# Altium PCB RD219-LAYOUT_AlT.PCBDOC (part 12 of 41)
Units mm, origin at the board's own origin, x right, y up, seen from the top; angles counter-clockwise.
Board outline 209.75 x 159.97 mm, 2 copper layers (TOP, BOTTOM), stack 0 mm thick; 398 components, 199 nets, 1469 pads, 0 vias.
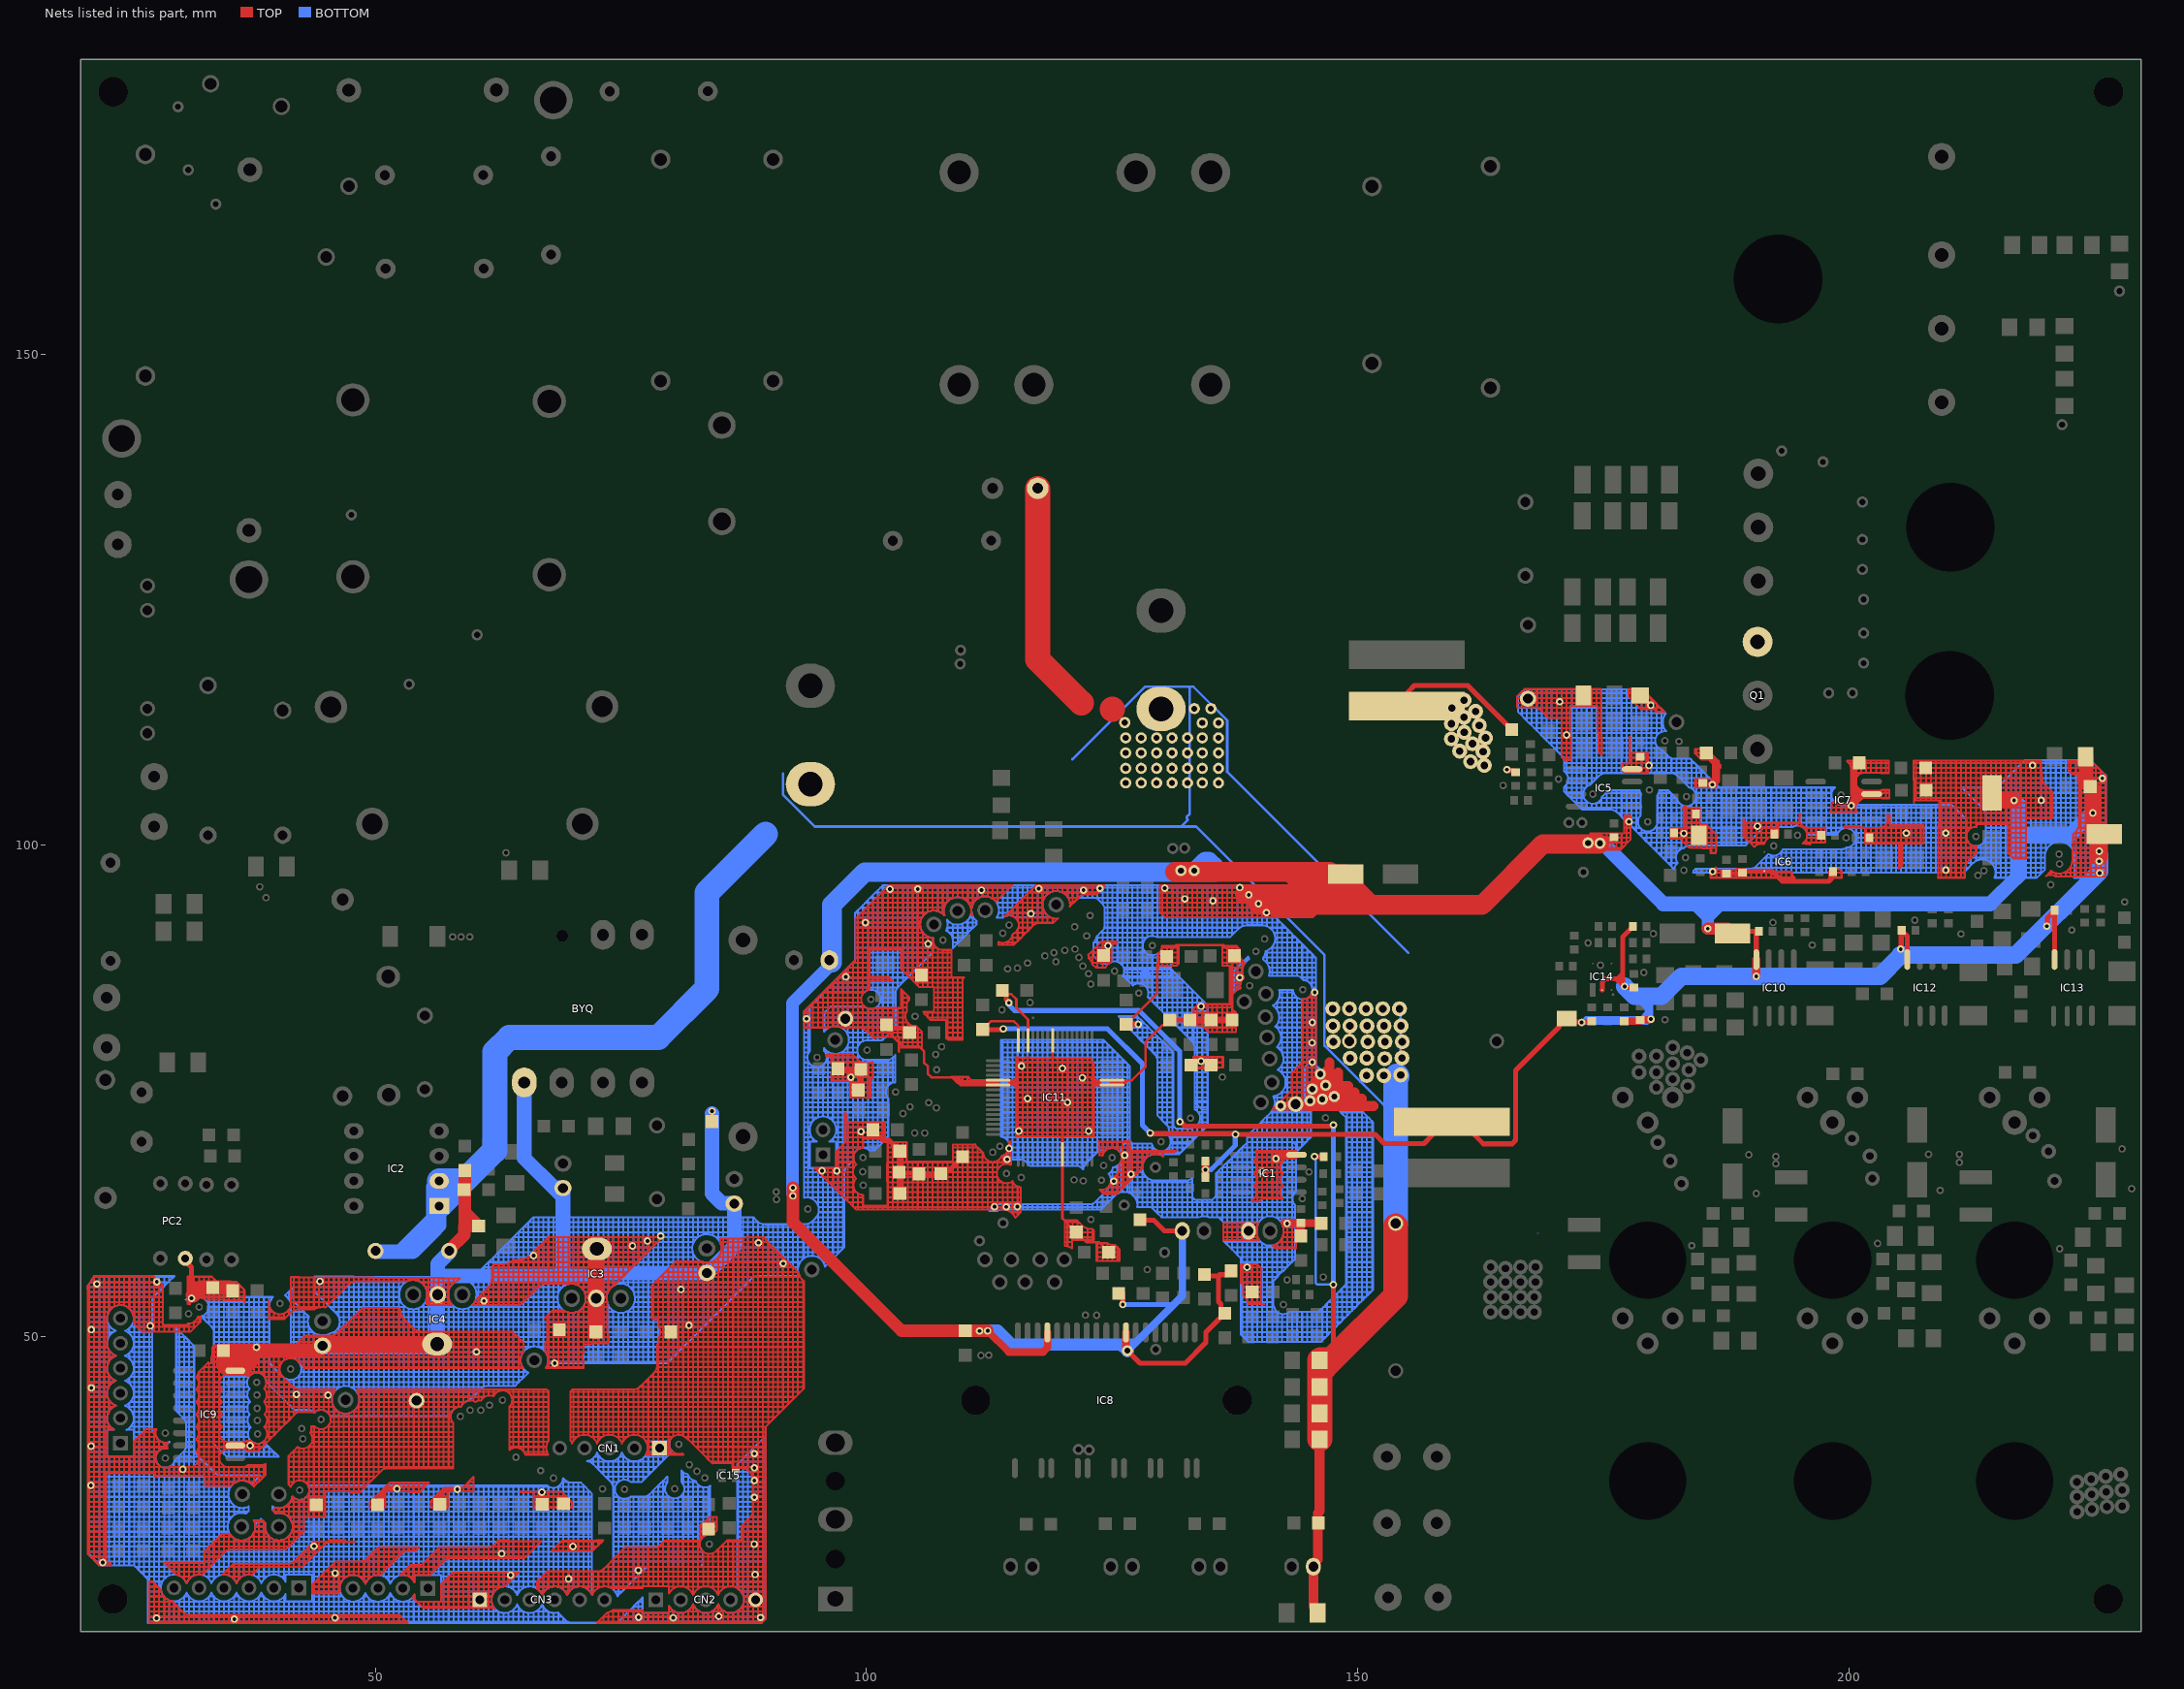
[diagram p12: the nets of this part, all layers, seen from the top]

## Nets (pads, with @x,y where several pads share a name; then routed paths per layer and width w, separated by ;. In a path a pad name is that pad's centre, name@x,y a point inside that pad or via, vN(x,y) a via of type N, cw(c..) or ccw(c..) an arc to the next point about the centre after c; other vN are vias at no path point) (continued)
GND: (continued)
  TOP w0.203: 90.993,56.576 90.993,57.084 ; 90.993,56.576 91.501,56.576 ; 90.993,57.084 90.993,57.592 ; 90.993,57.084 pad.@91.501,57.084 ; 90.993,57.592 90.993,58.1 ; 90.993,57.592 pad.@91.501,57.592 ; 90.993,58.1 91.501,58.1 ; 90.993,58.1 90.993,58.608 ; 90.993,58.608 91.006,58.608 ; 90.993,58.608 90.993,58.621 ; 90.993,58.621 91.006,58.608 ; 91.006,58.608 91.501,58.113 ; 91.247,42.352 91.501,42.606 ; 91.501,42.606 91.501,42.86 ; 91.501,42.606 91.755,42.86 ; 91.501,42.86 91.501,43.368 ; 91.501,42.86 91.755,42.86 ; 91.501,43.368 91.501,43.876 ; 91.501,43.368 92.009,43.368 ; 91.501,43.876 91.501,44.384 ; 91.501,43.876 92.009,43.876 ; 91.501,44.384 91.501,44.892 ; 91.501,44.384 92.009,44.384 ; 91.501,44.892 91.501,45.4 ; 91.501,44.892 92.009,44.892 ; 91.501,45.4 91.501,45.908 ; 91.501,45.4 92.009,45.4 ; 91.501,45.908 91.501,46.416 ; 91.501,45.908 92.009,45.908 ; 91.501,46.416 91.501,46.924 ; 91.501,46.416 92.009,46.416 ; 91.501,46.924 91.501,47.432 ; 91.501,46.924 92.009,46.924 ; 91.501,47.432 91.501,47.94 ; 91.501,47.432 92.009,47.432 ; 91.501,47.94 91.501,48.448 ; 91.501,47.94 92.009,47.94 ; 91.501,48.448 91.501,48.956 ; 91.501,48.448 92.009,48.448 ; 91.501,48.956 91.501,49.464 ; 91.501,48.956 92.009,48.956 ; 91.501,49.464 91.501,49.972 ; 91.501,49.464 92.009,49.464 ; 91.501,49.972 91.501,50.48 ; 91.501,49.972 92.009,49.972 ; 91.501,50.48 91.501,50.988 ; 91.501,50.48 92.009,50.48 ; 91.501,50.988 91.501,51.496 ; 91.501,50.988 92.009,50.988 ; 91.501,51.496 91.501,52.004 ; 91.501,51.496 92.009,51.496 ; 91.501,52.004 91.501,52.512 ; 91.501,52.004 92.009,52.004 ; 91.501,52.512 91.501,53.02 ; 91.501,52.512 92.009,52.512 ; 91.501,53.02 91.501,53.528 ; 91.501,53.02 92.009,53.02 ; 91.501,53.528 91.501,54.036 ; 91.501,53.528 92.009,53.528 ; 91.501,54.036 91.501,54.544 ; 91.501,54.036 92.009,54.036 ; 91.501,54.544 91.501,55.052 ; 91.501,54.544 92.009,54.544 ; 91.501,55.052 91.501,55.56 ; 91.501,55.052 92.009,55.052 ; 91.501,55.56 91.501,56.068 ; 91.501,55.56 92.009,55.56 ; 91.501,56.068 91.501,56.576 ; 91.501,56.068 92.009,56.068 ; 91.501,56.576 pad.@91.501,57.084 ; 91.501,56.576 92.009,56.576 ; pad.@91.501,57.084 pad.@91.501,57.592 ; pad.@91.501,57.084 92.009,57.084 ; pad.@91.501,57.592 91.501,58.1 ; pad.@91.501,57.592 92.009,57.592 ; 91.501,58.1 91.514,58.1 ; 91.501,58.1 91.501,58.113 ; 91.501,58.113 91.514,58.1 ; 91.514,58.1 92.009,57.605 ; 91.755,42.86 92.009,43.114 ; 92.009,43.114 92.009,43.368 ; 92.009,43.114 92.263,43.368 ; 92.009,43.368 92.009,43.876 ; 92.009,43.368 92.263,43.368 ; 92.009,43.876 92.009,44.384 ; 92.009,43.876 92.517,43.876 ; 92.009,44.384 92.009,44.892 ; 92.009,44.384 92.517,44.384 ; 92.009,44.892 92.009,45.4 ; 92.009,44.892 92.517,44.892 ; 92.009,45.4 92.009,45.908 ; 92.009,45.4 92.517,45.4 ; 92.009,45.908 92.009,46.416 ; 92.009,45.908 92.517,45.908 ; 92.009,46.416 92.009,46.924 ; 92.009,46.416 92.517,46.416 ; 92.009,46.924 92.009,47.432 ; 92.009,46.924 92.517,46.924 ; 92.009,47.432 92.009,47.94 ; 92.009,47.432 92.517,47.432 ; 92.009,47.94 92.009,48.448 ; 92.009,47.94 92.517,47.94 ; 92.009,48.448 92.009,48.956 ; 92.009,48.448 92.517,48.448 ; 92.009,48.956 92.009,49.464 ; 92.009,48.956 92.517,48.956 ; 92.009,49.464 92.009,49.972 ; 92.009,49.464 92.517,49.464 ; 92.009,49.972 92.009,50.48 ; 92.009,49.972 92.517,49.972 ; 92.009,50.48 92.009,50.988 ; 92.009,50.48 92.517,50.48 ; 92.009,50.988 92.009,51.496 ; 92.009,50.988 92.517,50.988 ; 92.009,51.496 92.009,52.004 ; 92.009,51.496 92.517,51.496 ; 92.009,52.004 92.009,52.512 ; 92.009,52.004 92.517,52.004 ; 92.009,52.512 92.009,53.02 ; 92.009,52.512 92.517,52.512 ; 92.009,53.02 92.009,53.528 ; 92.009,53.02 92.517,53.02 ; 92.009,53.528 92.009,54.036 ; 92.009,53.528 92.517,53.528 ; 92.009,54.036 92.009,54.544 ; 92.009,54.036 92.517,54.036 ; 92.009,54.544 92.009,55.052 ; 92.009,54.544 92.517,54.544 ; 92.009,55.052 92.009,55.56 ; 92.009,55.052 92.517,55.052 ; 92.009,55.56 92.009,56.068 ; 92.009,55.56 92.517,55.56 ; 92.009,56.068 92.009,56.576 ; 92.009,56.068 92.517,56.068 ; 92.009,56.576 92.009,57.084 ; 92.009,56.576 92.517,56.576 ; 92.009,57.084 92.009,57.592 ; 92.009,57.084 92.517,57.084 ; 92.009,57.592 92.009,57.605 ; 92.009,57.592 92.022,57.592 ; 92.009,57.605 92.022,57.592 ; 92.022,57.592 92.517,57.097 ; 92.263,43.368 92.517,43.622 ; 92.517,43.622 92.517,43.876 ; 92.517,43.622 92.771,43.876 ; 92.517,43.876 92.517,44.384 ; 92.517,43.876 92.771,43.876 ; 92.517,44.384 93.025,44.384 ; 92.517,44.384 92.517,44.892 ; 92.517,44.892 93.025,44.892 ; 92.517,44.892 92.517,45.4 ; 92.517,45.4 92.517,45.908 ; 92.517,45.4 93.025,45.4 ; 92.517,45.908 92.517,46.416 ; 92.517,45.908 93.025,45.908 ; 92.517,46.416 93.025,46.416 ; 92.517,46.416 92.517,46.924 ; 92.517,46.924 93.025,46.924 ; 92.517,46.924 92.517,47.432 ; 92.517,47.432 92.517,47.94 ; 92.517,47.432 93.025,47.432 ; 92.517,47.94 92.517,48.448 ; 92.517,47.94 93.025,47.94 ; 92.517,48.448 92.517,48.956 ; 92.517,48.448 93.025,48.448 ; 92.517,48.956 92.517,49.464 ; 92.517,48.956 93.025,48.956 ; 92.517,49.464 92.517,49.972 ; 92.517,49.464 93.025,49.464 ; 92.517,49.972 93.025,49.972 ; 92.517,49.972 92.517,50.48 ; 92.517,50.48 92.517,50.988 ; 92.517,50.48 93.025,50.48 ; 92.517,50.988 93.025,50.988 ; 92.517,50.988 92.517,51.496 ; 92.517,51.496 92.517,52.004 ; 92.517,51.496 93.025,51.496 ; 92.517,52.004 93.025,52.004 ; 92.517,52.004 92.517,52.512 ; 92.517,52.512 92.517,53.02 ; 92.517,52.512 93.025,52.512 ; 92.517,53.02 93.025,53.02 ; 92.517,53.02 92.517,53.528 ; 92.517,53.528 92.517,54.036 ; 92.517,53.528 93.025,53.528 ; 92.517,54.036 92.517,54.544 ; 92.517,54.036 93.025,54.036 ; 92.517,54.544 92.517,55.052 ; 92.517,54.544 93.025,54.544 ; 92.517,55.052 93.025,55.052 ; 92.517,55.052 92.517,55.56 ; 92.517,55.56 93.025,55.56 ; 92.517,55.56 92.517,56.068 ; 92.517,56.068 92.517,56.576 ; 92.517,56.068 93.025,56.068 ; 92.517,56.576 93.025,56.576 ; 92.517,56.576 92.517,57.084 ; 92.517,57.084 92.517,57.097 ; 92.517,57.084 92.53,57.084 ; 92.517,57.097 92.53,57.084 ; 92.53,57.084 93.025,56.589 ; 92.771,43.876 93.025,44.13 ; 93.025,44.13 93.279,44.384 ; 93.025,44.13 93.025,44.384 ; 93.025,44.384 93.279,44.384 ; 93.025,44.384 93.025,44.892 ; 93.025,44.892 93.533,44.892 ; 93.025,44.892 93.025,45.4 ; 93.025,45.4 93.025,45.908 ; 93.025,45.4 93.533,45.4 ; 93.025,45.908 93.025,46.416 ; 93.025,45.908 93.533,45.908 ; 93.025,46.416 93.533,46.416 ; 93.025,46.416 93.025,46.924 ; 93.025,46.924 93.533,46.924 ; 93.025,46.924 93.025,47.432 ; 93.025,47.432 93.025,47.94 ; 93.025,47.432 93.533,47.432 ; 93.025,47.94 93.025,48.448 ; 93.025,47.94 93.533,47.94 ; 93.025,48.448 93.025,48.956 ; 93.025,48.448 93.533,48.448 ; 93.025,48.956 93.025,49.464 ; 93.025,48.956 93.533,48.956 ; 93.025,49.464 93.025,49.972 ; 93.025,49.464 93.533,49.464 ; 93.025,49.972 93.533,49.972 ; 93.025,49.972 93.025,50.48 ; 93.025,50.48 93.025,50.988 ; 93.025,50.48 93.533,50.48 ; 93.025,50.988 93.533,50.988 ; 93.025,50.988 93.025,51.496 ; 93.025,51.496 93.025,52.004 ; 93.025,51.496 93.533,51.496 ; 93.025,52.004 93.533,52.004 ; 93.025,52.004 93.025,52.512 ; 93.025,52.512 93.025,53.02 ; 93.025,52.512 93.533,52.512 ; 93.025,53.02 93.533,53.02 ; 93.025,53.02 93.025,53.528 ; 93.025,53.528 93.025,54.036 ; 93.025,53.528 93.533,53.528 ; 93.025,54.036 93.025,54.544 ; 93.025,54.036 93.533,54.036 ; 93.025,54.544 93.025,55.052 ; 93.025,54.544 93.533,54.544 ; 93.025,55.052 93.533,55.052 ; 93.025,55.052 93.025,55.56 ; 93.025,55.56 93.533,55.56 ; 93.025,55.56 93.025,56.068 ; 93.025,56.068 93.025,56.576 ; 93.025,56.068 93.246,56.068 ; 93.025,56.576 93.025,56.589 ; 93.025,56.576 93.038,56.576 ; 93.025,56.589 93.038,56.576 ; 93.246,56.068 ccw(c94.422,56.83) 93.247,56.067 ccw(c94.422,56.83) 93.533,55.746 ; 93.279,44.384 93.533,44.638 ; 93.533,44.638 93.533,44.892 ; 93.533,44.638 93.66,44.765 93.66,44.892 ; 93.533,44.892 93.533,45.4 ; 93.533,44.892 93.66,44.892 ; 93.533,45.4 93.533,45.908 ; 93.533,45.4 93.66,45.4 ; 93.533,45.908 93.533,46.416 ; 93.533,45.908 93.66,45.908 ; 93.533,46.416 93.533,46.924 ; 93.533,46.416 93.66,46.416 ; 93.533,46.924 93.533,47.432 ; 93.533,46.924 93.66,46.924 ; 93.533,47.432 93.533,47.94 ; 93.533,47.432 93.66,47.432 ; 93.533,47.94 93.533,48.448 ; 93.533,47.94 93.66,47.94 ; 93.533,48.448 93.533,48.956 ; 93.533,48.448 93.66,48.448 ; 93.533,48.956 93.533,49.464 ; 93.533,48.956 93.66,48.956 ; 93.533,49.464 93.533,49.972 ; 93.533,49.464 93.66,49.464 ; 93.533,49.972 93.533,50.48 ; 93.533,50.48 93.533,50.988 ; 93.533,50.48 93.66,50.48 ; 93.533,50.988 93.66,50.988 ; 93.533,50.988 93.533,51.496 ; 93.533,51.496 93.533,52.004 ; 93.533,51.496 93.66,51.496 ; 93.533,52.004 93.66,52.004 ; 93.533,52.004 93.533,52.512 ; 93.533,52.512 93.533,53.02 ; 93.533,52.512 93.66,52.512 ; 93.533,53.02 93.533,53.528 ; 93.533,53.02 93.66,53.02 ; 93.533,53.528 93.533,54.036 ; 93.533,53.528 93.66,53.528 ; 93.533,54.036 93.533,54.544 ; 93.533,54.036 93.66,54.036 ; 93.533,54.544 93.533,55.052 ; 93.533,54.544 93.66,54.544 ; 93.533,55.052 93.533,55.56 ; 93.533,55.052 93.66,55.052 ; 93.533,55.56 93.66,55.56 ; 93.533,55.56 93.533,55.746 ; 93.66,44.892 93.66,45.4 ; 93.66,45.4 93.66,45.908 ; 93.66,45.908 93.66,46.416 ; 93.66,46.416 93.66,46.924 ; 93.66,46.924 93.66,47.432 ; 93.66,47.432 93.66,47.94 ; 93.66,47.94 93.66,48.448 ; 93.66,48.448 93.66,48.956 ; 93.66,48.956 93.66,49.464 ; 93.66,49.464 93.66,50.48 ; 93.66,50.48 93.66,50.988 ; 93.66,50.988 93.66,51.496 ; 93.66,51.496 93.66,52.004 ; 93.66,52.004 93.66,52.512 ; 93.66,52.512 93.66,53.02 ; 93.66,53.02 93.66,53.528 ; 93.66,53.528 93.66,54.036 ; 93.66,54.036 93.66,54.544 ; 93.66,54.544 93.66,55.052 ; 93.66,55.052 93.66,55.56 ; 93.66,81.468 93.66,81.976 ; 93.66,81.468 93.66,81.44 94.041,81.44 ; 93.66,81.468 94.041,81.468 ; 93.66,81.976 94.041,81.976 ; 93.66,81.976 pad.@93.66,82.484 ; pad.@93.66,82.484 93.66,82.992 ; pad.@93.66,82.484 pad.@94.041,82.484 ; 93.66,82.992 93.66,83.119 94.041,83.5 ; 93.66,82.992 94.041,82.992 ; 94.041,81.44 94.041,81.468 ; 94.041,81.44 94.549,81.44 ; 94.041,81.468 94.041,81.976 ; 94.041,81.468 94.549,81.468 ; 94.041,81.976 94.549,81.976 ; 94.041,81.976 pad.@94.041,82.484 ; pad.@94.041,82.484 94.041,82.992 ; pad.@94.041,82.484 94.549,82.484 ; 94.041,82.992 94.041,83.5 ; 94.041,82.992 94.549,82.992 ; 94.041,83.5 94.549,83.5 ; 94.041,83.5 94.549,84.008 ; 94.549,81.44 94.549,81.468 ; 94.549,81.44 95.057,81.44 ; 94.549,81.468 94.549,81.976 ; 94.549,81.468 95.057,81.468 ; 94.549,81.976 94.549,82.484 ; 94.549,81.976 95.057,81.976 ; 94.549,82.484 94.549,82.992 ; 94.549,82.484 95.057,82.484 ; 94.549,82.992 94.549,83.5 ; 94.549,82.992 95.057,82.992 ; 94.549,83.5 94.549,84.008 ; 94.549,83.5 95.057,83.5 ; 94.549,84.008 95.057,84.516 ; 94.549,84.008 95.057,84.008 ; 95.057,66.821 pad.@95.142,66.736 ; 95.057,66.821 94.716,67.162 95.057,67.162 ; 95.057,66.821 95.057,67.162 ; 95.057,67.162 pad.@95.565,67.162 ; 95.057,81.44 95.057,81.468 ; 95.057,81.44 95.565,81.44 ; 95.057,81.468 95.057,81.976 ; 95.057,81.468 95.565,81.468 ; 95.057,81.976 95.057,82.484 ; 95.057,81.976 95.565,81.976 ; 95.057,82.484 95.057,82.992 ; 95.057,82.484 95.565,82.484 ; 95.057,82.992 95.057,83.5 ; 95.057,82.992 95.565,82.992 ; 95.057,83.5 95.057,84.008 ; 95.057,83.5 95.565,83.5 ; 95.057,84.008 95.057,84.516 ; 95.057,84.008 95.565,84.008 ; 95.057,84.516 95.565,85.024 ; 95.057,84.516 95.565,84.516 ; pad.@95.142,66.736 95.565,66.313 ; pad.@95.142,66.736 pad.@95.565,66.736 ; 95.565,66.313 pad.@95.565,66.736 ; 95.565,66.313 95.65,66.228 ; pad.@95.565,66.736 96.073,66.736 ; pad.@95.565,66.736 pad.@95.565,67.162 ; pad.@95.565,67.162 96.073,67.162 ; 95.565,81.44 96.073,81.44 ; 95.565,81.44 95.565,81.468 ; 95.565,81.468 96.073,81.468 ; 95.565,81.468 95.565,81.976 ; 95.565,81.976 95.565,82.484 ; 95.565,81.976 96.073,81.976 ; 95.565,82.484 95.565,82.992 ; 95.565,82.484 96.073,82.484 ; 95.565,82.992 96.073,82.992 ; 95.565,82.992 95.565,83.5 ; 95.565,83.5 95.565,84.008 ; 95.565,83.5 96.073,83.5 ; 95.565,84.008 95.565,84.516 ; 95.565,84.008 96.073,84.008 ; 95.565,84.516 95.565,85.024 ; 95.565,84.516 96.073,84.516 ; 95.565,85.024 96.073,85.532 ; 95.565,85.024 96.073,85.024 ; 95.65,66.228 96.073,65.805 ; 95.65,66.228 96.073,66.228 ; 95.941,78.529 96.073,78.529 ; 96.073,65.805 96.158,65.72 ; 96.073,65.805 96.073,66.228 ; 96.073,66.228 96.073,66.736 ; 96.073,66.228 96.581,66.228 ; 96.073,66.736 96.073,67.162 ; 96.073,66.736 96.581,66.736 ; 96.073,67.162 96.581,67.162 ; 96.073,78.529 96.436,78.529 96.436,78.42 ; 96.073,78.529 96.073,78.736 ; 96.073,78.736 96.581,78.736 ; 96.073,81.44 96.073,81.468 ; 96.073,81.44 96.174,81.44 cw(c96.809,80.19) 96.233,81.468 ; 96.073,81.468 96.073,81.976 ; 96.073,81.468 96.233,81.468 ; 96.073,81.976 96.073,82.484 ; 96.073,81.976 96.581,81.976 ; 96.073,82.484 96.073,82.992 ; 96.073,82.484 96.581,82.484 ; 96.073,82.992 96.073,83.5 ; 96.073,82.992 96.581,82.992 ; 96.073,83.5 96.073,84.008 ; 96.073,83.5 96.581,83.5 ; 96.073,84.008 96.073,84.516 ; 96.073,84.008 96.581,84.008 ; 96.073,84.516 96.073,85.024 ; 96.073,84.516 96.581,84.516 ; 96.073,85.024 96.073,85.532 ; 96.073,85.024 96.581,85.024 ; 96.073,85.532 96.581,86.04 ; 96.073,85.532 96.581,85.532 ; 96.158,65.72 96.581,65.72 ; 96.158,65.72 96.581,65.297 ; 96.233,81.468 cw(c96.809,80.19) 96.581,81.573 ; 96.436,76.388 96.581,76.388 ; 96.436,76.388 96.436,76.039 96.581,76.039 ; 96.436,77.912 R144.1@96.581,77.912 ; 96.436,77.912 96.436,78.42 ; 96.436,78.42 96.581,78.42 ; R144.1@96.481,76.896 ccw(c95.184,77.277) R144.1@96.53,77.404 ; R144.1@96.481,76.896 R144.1@96.581,76.896 ; R144.1@96.53,77.404 R144.1@96.581,77.404 ; 96.581,65.297 96.666,65.212 ; 96.581,65.297 96.581,65.72 ; 96.581,65.72 96.581,66.228 ; 96.581,65.72 97.089,65.72 ; 96.581,66.228 97.089,66.228 ; 96.581,66.228 96.581,66.736 ; 96.581,66.736 pad.@97.089,66.736 ; 96.581,66.736 96.581,67.162 ; 96.581,67.162 96.917,67.162 pad.@96.917,67.244 ; 96.581,76.039 97.089,76.039 ; 96.581,76.039 96.581,76.388 ; 96.581,76.388 97.089,76.388 ; 96.581,76.388 R144.1@96.581,76.896 ; R144.1@96.581,76.896 R144.1@97.089,76.896 ; R144.1@96.581,76.896 R144.1@96.581,77.404 ; R144.1@96.581,77.404 R144.1@97.089,77.404 ; R144.1@96.581,77.404 R144.1@96.581,77.912 ; R144.1@96.581,77.912 R144.1@97.089,77.912 ; R144.1@96.581,77.912 96.581,78.42 ; 96.581,78.42 97.089,78.42 ; 96.581,78.42 96.581,78.736 ; 96.581,78.736 97.089,78.736 ; 96.581,81.573 cw(c96.809,80.19) 96.59,81.575 cw(c96.809,80.19) 97.089,81.564 ; 96.581,81.573 96.581,81.976 ; 96.581,81.976 96.581,82.484 ; 96.581,81.976 97.089,81.976 ; 96.581,82.484 96.581,82.992 ; 96.581,82.484 TP32.1@97.089,82.484 ; 96.581,82.992 97.089,82.992 ; 96.581,82.992 96.581,83.5 ; 96.581,83.5 96.581,84.008 ; 96.581,83.5 97.089,83.5 ; 96.581,84.008 96.581,84.516 ; 96.581,84.008 97.089,84.008 ; 96.581,84.516 96.581,85.024 ; 96.581,84.516 97.089,84.516 ; 96.581,85.024 96.581,85.532 ; 96.581,85.024 97.089,85.024 ; 96.581,85.532 97.089,85.532 ; 96.581,85.532 96.581,86.04 ; 96.581,86.04 97.089,86.548 ; 96.581,86.04 97.089,86.04 ; 96.666,65.212 97.089,64.789 ; 96.666,65.212 97.089,65.212 ; pad.@96.917,67.244 96.917,67.752 ; pad.@96.917,67.244 97.089,67.244 ; 96.917,67.752 97.089,67.752 ; 96.917,67.752 96.917,68.26 ; 96.917,68.26 96.917,68.768 ; 96.917,68.26 97.089,68.26 ; 96.917,68.768 97.089,68.768 ; 96.917,68.768 96.917,68.835 97.089,69.008 ; 97.089,64.789 97.174,64.704 ; 97.089,64.789 97.089,65.212 ; 97.089,65.212 97.089,65.72 ; 97.089,65.212 97.597,65.212 ; 97.089,65.72 97.089,66.228 ; 97.089,65.72 97.597,65.72 ; 97.089,66.228 pad.@97.089,66.736 ; 97.089,66.228 97.597,66.228 ; pad.@97.089,66.736 97.597,66.736 ; pad.@97.089,66.736 97.089,67.244 ; 97.089,67.244 97.089,67.752 ; 97.089,67.244 97.597,67.244 ; 97.089,67.752 97.089,68.26 ; 97.089,67.752 97.597,67.752 ; 97.089,68.26 97.089,68.768 ; 97.089,68.26 97.597,68.26 ; 97.089,68.768 97.089,69.008 ; 97.089,68.768 97.597,68.768 ; 97.089,69.008 97.357,69.276 ; 97.089,76.039 97.597,76.039 ; 97.089,76.039 97.089,76.388 ; 97.089,76.388 97.597,76.388 ; 97.089,76.388 R144.1@97.089,76.896 ; R144.1@97.089,76.896 R144.1@97.089,77.404 ; R144.1@97.089,76.896 R144.1@97.597,76.896 ; R144.1@97.089,77.404 R144.1@97.089,77.912 ; R144.1@97.089,77.404 R144.1@97.597,77.404 ; R144.1@97.089,77.912 97.089,78.42 ; R144.1@97.089,77.912 R144.1@97.597,77.912 ; 97.089,78.42 97.597,78.42 ; 97.089,78.42 97.089,78.736 ; 97.089,78.736 97.597,78.736 ; 97.089,81.564 cw(c96.809,80.19) 97.385,81.468 ; 97.089,81.564 97.089,81.976 ; 97.089,81.976 TP32.1@97.597,81.976 ; 97.089,81.976 TP32.1@97.089,82.484 ; TP32.1@97.089,82.484 97.089,82.992 ; TP32.1@97.089,82.484 TP32.1@97.597,82.484 ; 97.089,82.992 97.089,83.5 ; 97.089,82.992 TP32.1@97.597,82.992 ; 97.089,83.5 97.089,84.008 ; 97.089,83.5 97.597,83.5 ; 97.089,84.008 97.089,84.516 ; 97.089,84.008 97.597,84.008 ; 97.089,84.516 97.089,85.024 ; 97.089,84.516 97.597,84.516 ; 97.089,85.024 97.089,85.532 ; 97.089,85.024 97.597,85.024 ; 97.089,85.532 97.597,85.532 ; 97.089,85.532 97.089,86.04 ; 97.089,86.04 97.089,86.548 ; 97.089,86.04 97.597,86.04 ; 97.089,86.548 pad.@97.597,86.548 ; 97.089,86.548 97.597,87.056 ; 97.174,64.704 97.597,64.704 ; 97.174,64.704 97.597,64.281 ; 97.357,69.276 97.597,69.276 ; 97.357,69.276 97.597,69.516 ; 97.385,81.468 cw(c96.809,80.19) 97.445,81.44 97.597,81.44 ; 97.385,81.468 97.597,81.468 ; 97.597,64.281 97.597,64.704 ; 97.597,64.281 97.682,64.196 ; 97.597,64.704 98.105,64.704 ; 97.597,64.704 97.597,65.212 ; 97.597,65.212 97.597,65.72 ; 97.597,65.212 98.105,65.212 ; 97.597,65.72 97.597,66.228 ; 97.597,65.72 98.105,65.72 ; 97.597,66.228 97.597,66.736 ; 97.597,66.228 98.105,66.228 ; 97.597,66.736 97.597,67.244 ; 97.597,66.736 98.105,66.736 ; 97.597,67.244 97.597,67.752 ; 97.597,67.244 98.105,67.244 ; 97.597,67.752 97.597,68.26 ; 97.597,67.752 98.105,67.752 ; 97.597,68.26 97.597,68.768 ; 97.597,68.26 98.105,68.26 ; 97.597,68.768 97.597,69.276 ; 97.597,68.768 98.105,68.768 ; 97.597,69.276 98.105,69.276 ; 97.597,69.276 97.597,69.516 ; 97.597,69.516 97.604,69.523 ; 97.597,76.039 98.105,76.039 ; 97.597,76.039 97.597,76.388 ; 97.597,76.388 pad.@98.105,76.388 ; 97.597,76.388 R144.1@97.597,76.896 ; R144.1@97.597,76.896 98.105,76.896 ; R144.1@97.597,76.896 97.597,77.241 R144.1@97.597,77.404 ; R144.1@97.597,77.404 98.105,77.404 ; R144.1@97.597,77.404 R144.1@97.597,77.912 ; R144.1@97.597,77.912 98.105,77.912 ; R144.1@97.597,77.912 97.597,78.42 ; 97.597,78.42 98.105,78.42 ; 97.597,78.42 97.597,78.736 ; 97.597,78.736 98.105,78.736 ; 97.597,81.44 97.597,81.468 ; 97.597,81.44 98.105,81.44 ; 97.597,81.468 TP32.1@97.597,81.976 ; 97.597,81.468 98.105,81.468 ; TP32.1@97.597,81.976 TP32.1@97.597,82.484 ; TP32.1@97.597,81.976 TP32.1@98.105,81.976 ; TP32.1@97.597,82.484 TP32.1@97.597,82.992 ; TP32.1@97.597,82.484 TP32.1@98.105,82.484 ; TP32.1@97.597,82.992 97.597,83.5 ; TP32.1@97.597,82.992 TP32.1@98.105,82.992 ; 97.597,83.5 97.597,84.008 ; 97.597,83.5 98.105,83.5 ; 97.597,84.008 97.597,84.516 ; 97.597,84.008 98.105,84.008 ; 97.597,84.516 97.597,85.024 ; 97.597,84.516 98.105,84.516 ; 97.597,85.024 97.597,85.532 ; 97.597,85.024 98.105,85.024 ; 97.597,85.532 98.105,85.532 ; 97.597,85.532 97.597,86.04 ; 97.597,86.04 pad.@97.597,86.548 ; 97.597,86.04 98.105,86.04 ; pad.@97.597,86.548 pad.@98.105,86.548 ; pad.@97.597,86.548 97.597,87.056 ; 97.597,87.056 98.105,87.564 ; 97.597,87.056 98.105,87.056 ; 97.604,69.523 ccw(c97.089,70.038) 97.772,69.784 ; 97.604,69.523 ccw(c97.089,70.038) 97.772,69.784 ; 97.682,64.196 98.105,64.196 ; 97.682,64.196 98.105,63.773 ; 97.772,69.784 ccw(c97.089,70.038) 97.774,69.789 ; 97.772,69.784 ccw(c97.089,70.038) 97.774,69.789 ; 97.772,69.784 98.105,69.784 ; 97.774,69.789 ccw(c97.089,70.038) 97.818,70.038 ; 97.774,69.789 ccw(c97.089,70.038) 97.818,70.038 ; 97.818,70.038 97.818,70.292 ; 97.818,70.292 97.818,70.8 ; 97.818,70.292 98.105,70.292 ; 97.818,70.8 98.105,70.8 ; 97.818,70.8 97.818,71.308 ; 97.818,71.308 97.818,71.816 ; 97.818,71.308 98.105,71.308 ; 97.818,71.816 98.105,71.816 ; 97.818,71.816 97.818,72.324 ; 97.818,72.324 97.996,72.324 ; 97.996,72.324 97.996,71.834 98.105,71.834 ; 97.996,72.324 97.996,72.631 ; 97.996,72.631 cw(c98.366,73.259) 97.851,72.744 ccw(c98.366,73.259) 97.996,72.631 ; 97.996,72.631 ccw(c98.366,73.259) 98.002,72.628 cw(c98.366,73.259) 97.996,72.631 ; 98.105,63.773 98.105,64.196 ; 98.105,63.773 98.19,63.688 ; 98.105,64.196 98.105,64.704 ; 98.105,64.196 98.613,64.196 ; 98.105,64.704 98.105,65.212 ; 98.105,64.704 98.613,64.704 ; 98.105,65.212 98.105,65.72 ; 98.105,65.212 98.613,65.212 ; 98.105,65.72 98.105,66.228 ; 98.105,65.72 98.613,65.72 ; 98.105,66.228 98.105,66.736 ; 98.105,66.228 98.613,66.228 ; 98.105,66.736 98.105,67.244 ; 98.105,66.736 98.613,66.736 ; 98.105,67.244 98.105,67.752 ; 98.105,67.244 98.613,67.244 ; 98.105,67.752 98.105,68.26 ; 98.105,67.752 98.613,67.752 ; 98.105,68.26 98.105,68.768 ; 98.105,68.26 98.613,68.26 ; 98.105,68.768 98.105,69.276 ; 98.105,68.768 98.613,68.768 ; 98.105,69.276 98.105,69.784 ; 98.105,69.276 98.613,69.276 ; 98.105,69.784 98.105,70.292 ; 98.105,69.784 98.613,69.784 ; 98.105,70.292 98.105,70.8 ; 98.105,70.292 98.613,70.292 ; 98.105,70.8 98.105,71.308 ; 98.105,70.8 98.613,70.8 ; 98.105,71.308 98.105,71.816 ; 98.105,71.308 98.613,71.308 ; 98.105,71.816 98.105,71.834 ; 98.105,71.816 98.613,71.816 ; 98.105,71.834 98.613,71.834 ; 98.105,76.039 pad.@98.105,76.388 ; 98.105,76.039 98.341,76.039 98.341,75.88 ; pad.@98.105,76.388 98.105,76.896 ; pad.@98.105,76.388 pad.@98.613,76.388 ; 98.105,76.896 98.105,77.241 98.105,77.404 ; 98.105,76.896 98.613,76.896 ; 98.105,77.404 98.105,77.912 ; 98.105,77.404 98.613,77.404 ; 98.105,77.912 98.105,78.42 ; 98.105,77.912 98.613,77.912 ; 98.105,78.42 98.105,78.736 ; 98.105,78.42 98.613,78.42 ; 98.105,78.736 98.568,78.736 98.613,78.691 ; 98.105,81.44 98.105,81.468 ; 98.105,81.44 98.613,81.44 ; 98.105,81.468 TP32.1@98.105,81.976 ; 98.105,81.468 98.613,81.468 ; TP32.1@98.105,81.976 98.613,81.976 ; TP32.1@98.105,81.976 TP32.1@98.105,82.484 ; TP32.1@98.105,82.484 TP32.1@98.105,82.992 ; TP32.1@98.105,82.484 TP32.1@98.613,82.484 ; TP32.1@98.105,82.992 98.105,83.5 ; TP32.1@98.105,82.992 98.613,82.992 ; 98.105,83.5 98.105,84.008 ; 98.105,83.5 98.613,83.5 ; 98.105,84.008 98.105,84.516 ; 98.105,84.008 98.613,84.008 ; 98.105,84.516 98.105,85.024 ; 98.105,84.516 98.613,84.516 ; 98.105,85.024 98.105,85.532 ; 98.105,85.024 98.613,85.024 ; 98.105,85.532 98.105,86.04 ; 98.105,85.532 98.613,85.532 ; 98.105,86.04 pad.@98.105,86.548 ; 98.105,86.04 98.613,86.04 ; pad.@98.105,86.548 98.613,86.548 ; pad.@98.105,86.548 98.105,87.056 ; 98.105,87.056 98.105,87.564 ; 98.105,87.056 98.613,87.056 ; 98.105,87.564 98.613,88.072 ; 98.105,87.564 98.613,87.564 ; 98.19,63.688 98.613,63.265 ; 98.19,63.688 98.613,63.688 ; 98.341,74.356 98.613,74.356 ; 98.341,74.356 98.341,74.864 ; 98.341,74.356 98.341,74.338 98.613,74.338 ; 98.341,74.864 C88.2@98.613,74.864 ; 98.341,74.864 98.341,75.372 ; 98.341,75.372 98.341,75.88 ; 98.341,75.372 C88.2@98.613,75.372 ; 98.341,75.88 98.613,75.88 ; 98.613,63.265 98.698,63.18 ; 98.613,63.265 98.613,63.688 ; 98.613,63.688 99.121,63.688 ; 98.613,63.688 98.613,64.196 ; 98.613,64.196 99.121,64.196 ; 98.613,64.196 98.613,64.704 ; 98.613,64.704 98.613,65.212 ; 98.613,64.704 98.986,64.704 ; 98.613,65.212 98.613,65.72 ; 98.613,65.212 98.7,65.212 ; 98.613,65.72 98.613,66.228 ; 98.613,65.72 98.726,65.72 ; 98.613,66.228 98.613,66.736 ; 98.613,66.228 98.809,66.228 ; 98.613,66.736 98.613,67.244 ; 98.613,66.736 98.63,66.736 ; 98.613,67.244 98.613,67.752 ; 98.613,67.244 98.737,67.244 ; 98.613,67.752 98.613,68.26 ; 98.613,67.752 98.787,67.752 ; 98.613,68.26 98.613,68.768 ; 98.613,68.26 98.66,68.26 ; 98.613,68.768 98.613,69.276 ; 98.613,68.768 98.816,68.768 ; 98.613,69.276 98.613,69.784 ; 98.613,69.276 99.121,69.276 ; 98.613,69.784 98.613,70.292 ; 98.613,69.784 99.121,69.784 ; 98.613,70.292 98.613,70.8 ; 98.613,70.292 99.121,70.292 ; 98.613,70.8 98.613,71.308 ; 98.613,70.8 pad.@99.121,70.8 ; 98.613,71.308 98.613,71.816 ; 98.613,71.308 99.121,71.308 ; 98.613,71.816 98.613,71.834 ; 98.613,71.816 99.121,71.816 ; 98.613,71.834 99.121,71.834 ; 98.613,74.338 99.121,74.338 ; 98.613,74.338 98.613,74.356 ; 98.613,74.356 99.121,74.356 ; 98.613,74.356 C88.2@98.613,74.864 ; C88.2@98.613,74.864 C88.2@99.121,74.864 ; C88.2@98.613,74.864 C88.2@98.613,75.372 ; C88.2@98.613,75.372 98.613,75.88 ; C88.2@98.613,75.372 C88.2@99.121,75.372 ; 98.613,75.88 99.121,75.88 ; 98.613,75.88 pad.@98.613,76.388 ; pad.@98.613,76.388 99.121,76.388 ; pad.@98.613,76.388 98.613,76.896 ; 98.613,76.896 98.613,77.241 98.613,77.404 ; 98.613,76.896 C99.2@99.121,76.896 ; 98.613,77.404 98.613,77.912 ; 98.613,77.404 C99.2@99.121,77.404 ; 98.613,77.912 98.613,78.42 ; 98.613,77.912 99.121,77.912 ; 98.613,78.42 98.613,78.691 ; 98.613,78.42 98.884,78.42 ; 98.613,78.691 98.884,78.42 ; 98.613,81.44 99.121,81.44 ; 98.613,81.44 98.613,81.468 ; 98.613,81.468 99.121,81.468 ; 98.613,81.468 98.613,81.976 ; 98.613,81.976 99.121,81.976 ; 98.613,81.976 TP32.1@98.613,82.484 ; TP32.1@98.613,82.484 98.613,82.992 ; TP32.1@98.613,82.484 99.121,82.484 ; 98.613,82.992 99.121,82.992 ; 98.613,82.992 98.613,83.5 ; 98.613,83.5 98.613,84.008 ; 98.613,83.5 99.121,83.5 ; 98.613,84.008 98.613,84.516 ; 98.613,84.008 99.121,84.008 ; 98.613,84.516 98.613,85.024 ; 98.613,84.516 99.121,84.516 ; 98.613,85.024 98.613,85.532 ; 98.613,85.024 99.121,85.024 ; 98.613,85.532 99.121,85.532 ; 98.613,85.532 98.613,86.04 ; 98.613,86.04 98.613,86.548 ; 98.613,86.04 99.121,86.04 ; 98.613,86.548 99.121,86.548 ; 98.613,86.548 98.613,87.056 ; 98.613,87.056 99.121,87.056 ; 98.613,87.056 98.613,87.564 ; 98.613,87.564 98.613,88.072 ; 98.613,87.564 99.121,87.564 ; 98.613,88.072 98.867,88.326 98.867,88.58 ; 98.613,88.072 99.121,88.072 ; 98.63,66.736 ccw(c99.611,66.795) 98.809,66.228 ; 98.63,66.736 cw(c99.611,66.795) 98.628,66.795 cw(c99.611,66.795) 98.737,67.244 ; 98.66,68.26 ccw(c99.642,68.236) 98.66,68.236 ccw(c99.642,68.236) 98.787,67.752 ; 98.66,68.26 cw(c99.642,68.236) 98.816,68.768 ; 98.698,63.18 99.121,63.18 ; 98.698,63.18 98.946,62.932 99.121,62.932 ; 98.7,65.212 ccw(c99.661,65.418) 98.986,64.704 ; 98.7,65.212 cw(c99.661,65.418) 98.7,65.213 cw(c99.661,65.418) 98.679,65.418 cw(c99.661,65.418) 98.726,65.72 ; 98.816,68.768 cw(c99.642,68.236) 99.121,69.069 ; 98.867,88.58 99.121,88.58 ; 98.867,88.58 98.867,89.088 ; 98.867,89.088 99.121,89.088 ; 98.867,89.088 98.867,89.596 ; 98.867,89.596 99.121,89.596 ; 98.867,89.596 98.867,90.104 ; 98.867,90.104 99.121,90.104 ; 98.867,90.104 98.867,90.612 ; 98.867,90.612 99.121,90.612 ; 98.867,90.612 98.867,91.12 ; 98.867,91.12 99.121,91.12 ; 98.867,91.12 98.867,91.628 ; 98.867,91.628 99.121,91.628 ; 98.867,91.628 98.867,92.136 ; 98.867,92.136 99.121,92.136 ; 98.867,92.136 98.867,92.517 98.994,92.644 ; 98.884,78.42 99.095,78.209 ccw(c100.051,79.165) 99.121,78.184 ; 98.986,64.704 ccw(c99.661,65.418) 99.121,64.597 ; 98.994,92.644 99.121,92.771 ; 98.994,92.644 99.121,92.644 ; 99.121,62.932 99.629,62.932 ; 99.121,62.932 99.121,63.18 ; 99.121,63.18 99.121,63.688 ; 99.121,63.18 99.629,63.18 ; 99.121,63.688 99.629,63.688 ; 99.121,63.688 99.121,64.196 ; 99.121,64.196 99.629,64.196 ; 99.121,64.196 99.121,64.597 ; 99.121,64.597 ccw(c99.661,65.418) 99.629,64.436 ; 99.121,69.069 cw(c99.642,68.236) 99.629,69.218 ; 99.121,69.069 99.121,69.276 ; 99.121,69.276 99.629,69.276 ; 99.121,69.276 99.121,69.784 ; 99.121,69.784 99.121,70.292 ; 99.121,69.784 99.629,69.784 ; 99.121,70.292 99.629,70.292 ; 99.121,70.292 pad.@99.121,70.8 ; pad.@99.121,70.8 99.121,71.308 ; pad.@99.121,70.8 pad.@99.629,70.8 ; 99.121,71.308 99.121,71.816 ; 99.121,71.308 99.629,71.308 ; 99.121,71.816 99.629,71.816 ; 99.121,71.816 99.121,71.834 ; 99.121,71.834 99.629,71.834 ; 99.121,74.338 99.629,74.338 ; 99.121,74.338 99.121,74.356 ; 99.121,74.356 C88.2@99.121,74.864 ; 99.121,74.356 99.629,74.356 ; C88.2@99.121,74.864 C88.2@99.121,75.372 ; C88.2@99.121,74.864 C88.2@99.629,74.864 ; C88.2@99.121,75.372 99.121,75.88 ; C88.2@99.121,75.372 99.283,75.372 C88.2@99.629,75.372 ; 99.121,75.88 99.121,76.388 ; 99.121,75.88 99.283,75.88 99.629,75.88 ; 99.121,76.388 C99.2@99.121,76.896 ; 99.121,76.388 99.283,76.388 99.629,76.388 ; C99.2@99.121,76.896 99.283,76.896 C99.2@99.629,76.896 ; C99.2@99.121,76.896 99.121,77.241 C99.2@99.121,77.404 ; C99.2@99.121,77.404 99.121,77.912 ; C99.2@99.121,77.404 C99.2@99.629,77.404 ; 99.121,77.912 99.121,78.184 ; 99.121,77.912 99.544,77.912 ; 99.121,78.184 ccw(c100.051,79.165) 99.544,77.912 ; 99.121,81.44 99.121,81.468 ; 99.121,81.44 99.128,81.44 ; 99.121,81.468 99.629,81.468 ; 99.121,81.468 99.121,81.976 ; 99.121,81.976 99.121,82.484 ; 99.121,81.976 99.629,81.976 ; 99.121,82.484 99.121,82.992 ; 99.121,82.484 99.629,82.484 ; 99.121,82.992 99.629,82.992 ; 99.121,82.992 99.121,83.5 ; 99.121,83.5 99.121,84.008 ; 99.121,83.5 99.629,83.5 ; 99.121,84.008 99.121,84.516 ; 99.121,84.008 99.517,84.008 ; 99.121,84.516 99.121,85.024 ; 99.121,84.516 99.478,84.516 ; 99.121,85.024 99.629,85.024 ; 99.121,85.024 99.121,85.532 ; 99.121,85.532 99.629,85.532 ; 99.121,85.532 99.121,86.04 ; 99.121,86.04 99.121,86.548 ; 99.121,86.04 99.629,86.04 ; 99.121,86.548 99.121,87.056 ; 99.121,86.548 99.629,86.548 ; 99.121,87.056 99.121,87.564 ; 99.121,87.056 99.629,87.056 ; 99.121,87.564 99.121,88.072 ; 99.121,87.564 99.629,87.564 ; 99.121,88.072 99.121,88.58 ; 99.121,88.072 99.629,88.072 ; 99.121,88.58 99.121,89.088 ; 99.121,88.58 99.629,88.58 ; 99.121,89.088 99.121,89.596 ; 99.121,89.088 99.629,89.088 ; 99.121,89.596 99.121,90.104 ; 99.121,89.596 99.629,89.596 ; 99.121,90.104 99.121,90.612 ; 99.121,90.104 99.629,90.104 ; 99.121,90.612 99.121,91.12 ; 99.121,90.612 99.629,90.612 ; 99.121,91.12 99.121,91.628 ; 99.121,91.12 99.629,91.12 ; 99.121,91.628 99.121,92.136 ; 99.121,91.628 99.629,91.628 ; 99.121,92.136 99.121,92.644 ; 99.121,92.136 pad.@99.629,92.136 ; 99.121,92.644 99.629,92.644 ; 99.121,92.644 99.121,92.771 ; 99.121,92.771 99.502,93.152 ; 99.128,81.44 cw(c99.128,80.088) 99.629,81.343 ; 99.128,81.44 cw(c99.128,80.088) 99.629,81.343 ; 99.478,84.516 ccw(c100.444,84.334) 99.515,84.014 ccw(c100.444,84.334) 99.517,84.008 ; 99.478,84.516 cw(c100.444,84.334) 99.479,84.521 cw(c100.444,84.334) 99.629,84.883 ; 99.502,93.152 99.629,93.152 ; 99.502,93.152 99.629,93.279 ; 99.517,84.008 ccw(c100.444,84.334) 99.629,83.784 ; 99.544,77.912 ccw(c100.051,79.165) 99.629,77.881 ; 99.629,62.932 100.137,62.932 ; 99.629,62.932 99.629,63.18 ; 99.629,63.18 99.629,63.688 ; 99.629,63.18 100.137,63.18 ; 99.629,63.688 99.647,63.688 ; 99.629,63.688 99.629,64.196 ; 99.629,64.196 99.647,64.196 ; 99.629,64.196 99.629,64.436 ; 99.629,69.218 99.629,69.276 ; 99.629,69.276 99.629,69.784 ; 99.629,69.276 99.647,69.276 ; 99.629,69.784 99.629,70.292 ; 99.629,69.784 99.647,69.784 ; 99.629,70.292 pad.@99.629,70.8 ; 99.629,70.292 100.137,70.292 ; pad.@99.629,70.8 C12.2@100.137,70.8 ; pad.@99.629,70.8 99.629,71.308 ; 99.629,71.308 99.629,71.816 ; 99.629,71.308 C12.2@100.137,71.308 ; 99.629,71.816 99.629,71.834 ; 99.629,71.816 100.137,71.816 ; 99.629,71.834 100.137,71.834 ; 99.629,74.338 99.629,74.356 ; 99.629,74.338 100.137,74.338 ; 99.629,74.356 C88.2@99.629,74.864 ; 99.629,74.356 100.137,74.356 ; C88.2@99.629,74.864 100.137,74.864 ; C88.2@99.629,74.864 C88.2@99.629,75.372 ; C88.2@99.629,75.372 99.629,75.88 ; C88.2@99.629,75.372 100.137,75.372 ; 99.629,75.88 99.629,76.388 ; 99.629,75.88 100.137,75.88 ; 99.629,76.388 C99.2@99.629,76.896 ; 99.629,76.388 100.137,76.388 ; C99.2@99.629,76.896 100.137,76.896 ; C99.2@99.629,76.896 C99.2@99.629,77.404 ; C99.2@99.629,77.404 100.137,77.404 ; C99.2@99.629,77.404 99.629,77.881 ; 99.629,77.881 ccw(c100.051,79.165) 100.137,77.816 ; 99.629,81.343 cw(c99.128,80.088) 99.634,81.341 ; 99.629,81.343 cw(c99.128,80.088) 99.634,81.341 ; 99.629,81.343 99.629,81.468 ; 99.629,81.468 100.137,81.468 ; 99.629,81.468 99.629,81.976 ; 99.629,81.976 99.629,82.484 ; 99.629,81.976 100.137,81.976 ; 99.629,82.484 99.629,82.992 ; 99.629,82.484 100.137,82.484 ; 99.629,82.992 100.137,82.992 ; 99.629,82.992 99.629,83.5 ; 99.629,83.5 99.629,83.784 ; 99.629,83.5 99.924,83.5 ccw(c100.444,84.334) 100.137,83.4 ; 99.629,84.883 cw(c100.444,84.334) 99.744,85.024 ; 99.629,84.883 99.629,85.024 ; 99.629,85.024 99.629,85.532 ; 99.629,85.024 99.744,85.024 ; 99.629,85.532 100.137,85.532 ; 99.629,85.532 99.629,86.04 ; 99.629,86.04 99.629,86.548 ; 99.629,86.04 100.137,86.04 ; 99.629,86.548 100.137,86.548 ; 99.629,86.548 99.629,87.056 ; 99.629,87.056 100.137,87.056 ; 99.629,87.056 99.629,87.564 ; 99.629,87.564 99.629,88.072 ; 99.629,87.564 100.137,87.564 ; 99.629,88.072 99.629,88.58 ; 99.629,88.072 100.137,88.072 ; 99.629,88.58 99.629,89.088 ; 99.629,88.58 100.137,88.58 ; 99.629,89.088 99.629,89.596 ; 99.629,89.088 100.137,89.088 ; 99.629,89.596 99.629,90.104 ; 99.629,89.596 100.137,89.596 ; 99.629,90.104 99.629,90.612 ; 99.629,90.104 100.137,90.104 ; 99.629,90.612 99.629,91.12 ; 99.629,90.612 100.137,90.612 ; 99.629,91.12 99.629,91.628 ; 99.629,91.12 100.137,91.12 ; 99.629,91.628 100.137,91.628 ; 99.629,91.628 pad.@99.629,92.136 ; pad.@99.629,92.136 pad.@99.883,92.136 pad.@100.137,92.136 ; pad.@99.629,92.136 99.629,92.644 ; 99.629,92.644 100.137,92.644 ; 99.629,92.644 99.629,93.152 ; 99.629,93.152 100.137,93.152 ; 99.629,93.152 99.629,93.279 ; 99.629,93.279 100.01,93.66 ; 99.634,81.341 cw(c99.128,80.088) 100.083,81.044 ccw(c99.128,80.088) 99.634,81.341 ; 99.647,63.688 99.647,64.196 ; 99.647,63.688 99.647,63.325 100.137,63.325 ; 99.647,69.276 99.647,69.784 ; 99.647,69.784 99.647,70.147 100.137,70.147 ; 99.744,85.024 cw(c100.444,84.334) 100.137,85.267 ; 100.01,93.66 100.137,93.66 ; 100.01,93.66 100.137,93.787 ; 100.137,62.932 100.137,63.18 ; 100.137,62.932 100.645,62.932 ; 100.137,63.18 100.137,63.325 ; 100.137,63.18 100.645,63.18 ; 100.137,63.325 100.645,63.325 ; 100.137,70.147 100.645,70.147 ; 100.137,70.147 100.137,70.292 ; 100.137,70.292 100.645,70.292 ; 100.137,70.292 C12.2@100.137,70.8 ; C12.2@100.137,70.8 C12.2@100.645,70.8 ; C12.2@100.137,70.8 C12.2@100.137,71.308 ; C12.2@100.137,71.308 C12.2@100.645,71.308 ; C12.2@100.137,71.308 100.137,71.816 ; 100.137,71.816 100.645,71.816 ; 100.137,71.816 100.137,71.834 ; 100.137,74.338 100.137,74.356 ; 100.137,74.338 100.389,74.338 100.389,74.356 ; 100.137,74.356 100.137,74.864 ; 100.137,74.356 100.389,74.356 ; 100.137,74.864 100.137,75.372 ; 100.137,74.864 100.389,74.864 ; 100.137,75.372 100.137,75.88 ; 100.137,75.372 100.389,75.372 ; 100.137,75.88 100.137,76.388 ; 100.137,75.88 100.389,75.88 ; 100.137,76.388 100.137,76.896 ; 100.137,76.388 100.645,76.388 ; 100.137,76.896 100.645,76.896 ; 100.137,76.896 100.137,77.404 ; 100.137,77.404 100.645,77.404 ; 100.137,77.404 100.137,77.816 ; 100.137,77.816 ccw(c100.051,79.165) 100.557,77.912 ; 100.137,80.99 100.167,80.96 ; 100.137,80.99 100.137,81.468 ; 100.137,81.468 100.645,81.468 ; 100.137,81.468 100.137,81.976 ; 100.137,81.976 100.137,82.484 ; 100.137,81.976 100.645,81.976 ; 100.137,82.484 100.137,82.992 ; 100.137,82.484 100.645,82.484 ; 100.137,82.992 100.645,82.992 ; 100.137,82.992 100.137,83.4 ; 100.137,83.4 ccw(c100.444,84.334) 100.645,83.372 ; 100.137,85.267 100.137,85.532 ; 100.137,85.532 100.137,86.04 ; 100.137,85.532 100.313,85.532 ; 100.137,86.04 100.137,86.548 ; 100.137,86.04 100.313,86.04 ; 100.137,86.548 100.645,86.548 ; 100.137,86.548 100.137,87.056 ; 100.137,87.056 100.313,87.056 ; 100.137,87.056 100.137,87.564 ; 100.137,87.564 100.137,88.072 ; 100.137,87.564 100.313,87.564 ; 100.137,88.072 100.137,88.58 ; 100.137,88.072 100.313,88.072 ; 100.137,88.58 100.137,89.088 ; 100.137,88.58 100.313,88.58 ; 100.137,89.088 100.137,89.596 ; 100.137,89.088 100.313,89.088 ; 100.137,89.596 100.137,90.104 ; 100.137,89.596 100.645,89.596 ; 100.137,90.104 100.137,90.612 ; 100.137,90.104 100.645,90.104 ; 100.137,90.612 100.137,91.12 ; 100.137,90.612 100.645,90.612 ; 100.137,91.12 100.137,91.628 ; 100.137,91.12 100.645,91.12 ; 100.137,91.628 100.645,91.628 ; 100.137,91.628 pad.@100.137,92.136 ; pad.@100.137,92.136 100.645,92.136 ; pad.@100.137,92.136 100.137,92.644 ; 100.137,92.644 100.645,92.644 ; 100.137,92.644 100.137,93.152 ; 100.137,93.152 100.137,93.66 ; 100.137,93.152 100.645,93.152 ; 100.137,93.66 100.137,93.787 ; 100.137,93.66 100.645,93.66 ; 100.137,93.787 100.518,94.168 ; 100.167,80.96 100.645,80.96 ; 100.167,80.96 100.645,80.482 ; 100.313,85.532 100.313,86.04 ; 100.313,86.04 100.313,86.245 100.645,86.245 ; 100.313,87.056 100.313,87.564 ; 100.313,87.056 100.313,86.597 100.645,86.597 ; 100.313,87.564 100.313,88.072 ; 100.313,88.072 100.313,88.58 ; 100.313,88.58 100.313,89.088 ; 100.313,89.088 100.313,89.401 100.645,89.401 ; 100.389,74.356 100.389,74.864 ; 100.389,74.864 100.389,75.372 ; 100.389,75.372 100.389,75.88 ; 100.389,75.88 100.389,76.349 100.645,76.349 ; 100.518,94.168 100.645,94.168 ; 100.518,94.168 100.645,94.295 ; 100.557,77.912 100.645,77.912 ; 100.645,62.932 100.645,63.18 ; 100.645,62.932 101.153,62.932 ; 100.645,63.18 100.645,63.325 ; 100.645,63.18 101.153,63.18 ; 100.645,63.325 101.153,63.325 ; 100.645,70.147 100.645,70.292 ; 100.645,70.147 101.153,70.147 ; 100.645,70.292 101.153,70.292 ; 100.645,70.292 C12.2@100.645,70.8 ; C12.2@100.645,70.8 100.899,70.8 C12.2@101.153,70.8 ; C12.2@100.645,70.8 C12.2@100.645,71.308 ; C12.2@100.645,71.308 100.645,71.816 ; C12.2@100.645,71.308 C12.2@101.153,71.308 ; 100.645,71.816 101.153,71.816 ; 100.645,71.816 100.645,71.834 ; 100.645,71.834 101.153,71.834 ; 100.645,76.349 100.652,76.349 100.652,76.388 ; 100.645,76.349 100.645,76.388 ; 100.645,76.388 100.645,76.896 ; 100.645,76.388 100.652,76.388 ; 100.645,76.896 100.645,77.404 ; 100.645,76.896 100.652,76.896 ; 100.645,77.404 100.645,77.912 ; 100.645,77.404 100.652,77.404 ; 100.645,77.912 100.652,77.912 ; 100.645,80.482 100.645,80.96 ; 100.645,80.482 100.675,80.452 ; 100.645,80.96 101.153,80.96 ; 100.645,80.96 100.645,81.468 ; 100.645,81.468 101.153,81.468 ; 100.645,81.468 100.645,81.976 ; 100.645,81.976 100.645,82.484 ; 100.645,81.976 101.153,81.976 ; 100.645,82.484 100.645,82.992 ; 100.645,82.484 101.153,82.484 ; 100.645,82.992 101.153,82.992 ; 100.645,82.992 100.645,83.372 ; 100.645,83.372 ccw(c100.444,84.334) 100.855,83.441 ; 100.645,86.245 100.645,86.548 ; 100.645,86.245 101.153,86.245 ; 100.645,86.548 100.645,86.597 ; 100.645,86.548 101.153,86.548 ; 100.645,86.597 101.153,86.597 ; 100.645,89.401 100.645,89.596 ; 100.645,89.401 101.153,89.401 ; 100.645,89.596 100.645,90.104 ; 100.645,89.596 101.153,89.596 ; 100.645,90.104 100.645,90.612 ; 100.645,90.104 101.153,90.104 ; 100.645,90.612 100.645,91.12 ; 100.645,90.612 101.153,90.612 ; 100.645,91.12 100.645,91.628 ; 100.645,91.12 101.153,91.12 ; 100.645,91.628 100.645,92.136 ; 100.645,91.628 101.153,91.628 ; 100.645,92.136 100.645,92.644 ; 100.645,92.136 101.153,92.136 ; 100.645,92.644 100.645,93.152 ; 100.645,92.644 101.153,92.644 ; 100.645,93.152 100.645,93.66 ; 100.645,93.152 101.153,93.152 ; 100.645,93.66 100.645,94.168 ; 100.645,93.66 101.153,93.66 ; 100.645,94.168 101.153,94.168 ; 100.645,94.168 100.645,94.295 ; 100.645,94.295 101.026,94.676 ; 100.652,76.388 100.652,76.896 ; 100.652,76.896 100.652,77.404 ; 100.652,77.404 100.652,77.912 ; 100.675,80.452 100.79,80.337 100.79,80.452 ; 100.675,80.452 100.79,80.452 ; 100.79,80.452 100.79,80.484 101.153,80.484 ; 100.855,83.441 101.153,83.441 ; 101.026,94.676 101.153,94.803 ; 101.026,94.676 101.153,94.676 ; 101.153,62.932 101.153,63.18 ; 101.153,62.932 101.661,62.932 ; 101.153,63.18 101.153,63.325 ; 101.153,63.18 101.661,63.18 ; 101.153,63.325 101.661,63.325 ; 101.153,70.147 101.552,70.147 101.661,70.147 ; 101.153,70.147 101.153,70.292 ; 101.153,70.292 101.407,70.292 101.661,70.292 ; 101.153,70.292 101.153,70.546 C12.2@101.153,70.8 ; C12.2@101.153,70.8 101.661,70.8 ; C12.2@101.153,70.8 C12.2@101.153,71.308 ; C12.2@101.153,71.308 101.153,71.816 ; C12.2@101.153,71.308 101.661,71.308 ; 101.153,71.816 101.661,71.816 ; 101.153,71.816 101.153,71.834 ; 101.153,71.834 101.661,71.834 ; 101.153,80.484 101.153,80.96 ; 101.153,80.484 101.661,80.484 ; 101.153,80.96 101.153,81.468 ; 101.153,80.96 101.661,80.96 ; 101.153,81.468 101.153,81.976 ; 101.153,81.468 C98.2@101.661,81.468 ; 101.153,81.976 101.153,82.484 ; 101.153,81.976 C98.2@101.661,81.976 ; 101.153,82.484 101.153,82.992 ; 101.153,82.484 101.661,82.484 ; 101.153,82.992 101.153,83.441 ; 101.153,82.992 101.661,82.992 ; 101.153,83.441 101.661,83.441 ; 101.153,86.245 101.153,86.548 ; 101.153,86.245 101.661,86.245 ; 101.153,86.548 101.153,86.597 ; 101.153,86.548 101.661,86.548 ; 101.153,86.597 101.661,86.597 ; 101.153,89.401 101.153,89.596 ; 101.153,89.401 101.661,89.401 ; 101.153,89.596 101.153,90.104 ; 101.153,89.596 101.661,89.596 ; 101.153,90.104 101.153,90.612 ; 101.153,90.104 101.661,90.104 ; 101.153,90.612 101.153,91.12 ; 101.153,90.612 101.661,90.612 ; 101.153,91.12 101.153,91.628 ; 101.153,91.12 101.661,91.12 ; 101.153,91.628 101.153,92.136 ; 101.153,91.628 101.661,91.628 ; 101.153,92.136 101.153,92.644 ; 101.153,92.136 101.661,92.136 ; 101.153,92.644 101.153,93.152 ; 101.153,92.644 101.661,92.644 ; 101.153,93.152 101.153,93.66 ; 101.153,93.152 101.661,93.152 ; 101.153,93.66 101.153,94.168 ; 101.153,93.66 101.661,93.66 ; 101.153,94.168 101.153,94.676 ; 101.153,94.168 101.661,94.168 ; 101.153,94.676 101.661,94.676 ; 101.153,94.676 101.153,94.803 ; 101.153,94.803 101.534,95.184 ; 101.534,95.184 101.661,95.311 ; 101.534,95.184 101.661,95.184 ; 101.661,62.932 102.169,62.932 ; 101.661,62.932 101.661,63.18 ; 101.661,63.18 101.661,63.325 ; 101.661,63.18 102.169,63.18 ; 101.661,63.325 102.151,63.325 102.151,63.688 ; 101.661,70.147 101.661,70.292 ; 101.661,70.147 101.883,70.147 101.883,70.292 ; 101.661,70.292 101.661,70.8 ; 101.661,70.292 101.883,70.292 ; 101.661,70.8 101.661,71.308 ; 101.661,70.8 101.883,70.8 ; 101.661,71.308 101.661,71.816 ; 101.661,71.308 101.883,71.308 ; 101.661,71.816 101.883,71.816 ; 101.661,71.816 101.661,71.834 ; 101.661,71.834 101.883,71.834 101.883,71.816 ; 101.661,80.484 101.661,80.96 ; 101.661,80.484 102.169,80.484 ; 101.661,80.96 C98.2@101.661,81.468 ; 101.661,80.96 102.169,80.96 ; C98.2@101.661,81.468 C98.2@101.661,81.976 ; C98.2@101.661,81.468 C98.2@102.169,81.468 ; C98.2@101.661,81.976 101.661,82.484 ; C98.2@101.661,81.976 C98.2@102.169,81.976 ; 101.661,82.484 101.661,82.992 ; 101.661,82.484 102.169,82.484 ; 101.661,82.992 101.661,83.441 ; 101.661,82.992 102.169,82.992 ; 101.661,83.441 102.169,83.441 ; 101.661,86.245 102.169,86.245 ; 101.661,86.245 101.661,86.548 ; 101.661,86.548 102.169,86.548 ; 101.661,86.548 101.661,86.597 ; 101.661,86.597 102.169,86.597 ; 101.661,89.401 102.169,89.401 ; 101.661,89.401 101.661,89.596 ; 101.661,89.596 101.661,90.104 ; 101.661,89.596 102.169,89.596 ; 101.661,90.104 101.661,90.612 ; 101.661,90.104 102.169,90.104 ; 101.661,90.612 101.661,91.12 ; 101.661,90.612 102.169,90.612 ; 101.661,91.12 101.661,91.628 ; 101.661,91.12 102.169,91.12 ; 101.661,91.628 101.661,92.136 ; 101.661,91.628 102.169,91.628 ; 101.661,92.136 101.661,92.644 ; 101.661,92.136 102.169,92.136 ; 101.661,92.644 102.169,92.644 ; 101.661,92.644 101.661,93.152 ; 101.661,93.152 101.661,93.66 ; 101.661,93.152 102.169,93.152 ; 101.661,93.66 102.169,93.66 ; 101.661,93.66 101.661,94.168 ; 101.661,94.168 101.661,94.676 ; 101.661,94.168 102.169,94.168 ; 101.661,94.676 101.661,95.184 ; 101.661,94.676 102.169,94.676 ; 101.661,95.184 101.661,95.311 ; 101.661,95.184 102.169,95.184 ; 101.661,95.311 pad.@102.042,95.692 ; 101.883,70.292 101.883,70.8 ; 101.883,70.8 101.883,71.308 ; 101.883,71.308 101.883,71.816 ; pad.@102.042,95.692 pad.@102.169,95.692 ; pad.@102.042,95.692 pad.@102.169,95.819 ; 102.074,66.228 102.169,66.228 ; 102.074,66.228 102.074,66.736 ; 102.074,66.736 102.169,66.736 ; 102.074,66.736 102.074,67.244 ; 102.074,67.244 102.169,67.244 ; 102.151,63.688 102.169,63.688 ; 102.151,63.688 102.151,64.196 ; 102.151,64.196 102.169,64.196 ; 102.151,64.196 102.151,64.704 ; 102.151,64.704 102.151,65.212 ; 102.151,64.704 102.169,64.704 ; 102.151,65.212 102.151,65.72 ; 102.151,65.212 102.169,65.212 ; 102.151,65.72 102.169,65.72 ; 102.151,67.752 102.151,68.26 ; 102.151,67.752 102.169,67.752 ; 102.151,68.26 102.151,68.768 ; 102.151,68.26 102.169,68.26 ; 102.151,68.768 102.169,68.768 ; 102.151,68.768 102.151,69.276 ; 102.151,69.276 102.169,69.276 ; 102.151,69.276 102.151,69.784 ; 102.151,69.784 102.169,69.784 ; 102.151,69.784 102.151,69.802 102.169,69.802 ; 102.169,62.932 102.677,62.932 ; 102.169,62.932 102.169,63.18 ; 102.169,63.18 102.169,63.688 ; 102.169,63.18 102.677,63.18 ; 102.169,63.688 102.169,64.196 ; 102.169,63.688 102.677,63.688 ; 102.169,64.196 102.169,64.704 ; 102.169,64.196 102.677,64.196 ; 102.169,64.704 102.169,65.212 ; 102.169,64.704 102.677,64.704 ; 102.169,65.212 102.169,65.72 ; 102.169,65.212 102.677,65.212 ; 102.169,65.72 102.169,66.228 ; 102.169,65.72 102.677,65.72 ; 102.169,66.228 C73.2@102.677,66.228 ; 102.169,66.228 102.169,66.736 ; 102.169,66.736 102.169,67.244 ; 102.169,66.736 C73.2@102.677,66.736 ; 102.169,67.244 102.169,67.752 ; 102.169,67.244 C73.2@102.677,67.244 ; 102.169,67.752 102.677,67.752 ; 102.169,67.752 102.169,68.26 ; 102.169,68.26 102.677,68.26 ; 102.169,68.26 102.169,68.768 ; 102.169,68.768 102.677,68.768 ; 102.169,68.768 102.169,69.276 ; 102.169,69.276 102.677,69.276 ; 102.169,69.276 102.169,69.784 ; 102.169,69.784 102.499,69.784 102.677,69.784 ; 102.169,69.784 102.169,69.802 ; 102.169,69.802 102.481,69.802 102.677,69.802 ; 102.169,80.484 102.169,80.96 ; 102.169,80.484 102.677,80.484 ; 102.169,80.96 102.367,80.96 102.677,80.96 ; 102.169,80.96 C98.2@102.169,81.468 ; C98.2@102.169,81.468 102.169,81.595 C98.2@102.169,81.976 ; C98.2@102.169,81.468 102.296,81.468 C98.2@102.677,81.468 ; C98.2@102.169,81.976 102.169,82.484 ; C98.2@102.169,81.976 C98.2@102.677,81.976 ; 102.169,82.484 102.169,82.992 ; 102.169,82.484 102.677,82.484 ; 102.169,82.992 102.169,83.441 ; 102.169,82.992 102.677,82.992 ; 102.169,83.441 102.677,83.441 ; 102.169,86.245 102.169,86.548 ; 102.169,86.245 102.636,86.245 102.332,86.548 ; 102.169,86.548 102.332,86.548 ; 102.169,86.548 102.169,86.597 ; 102.169,86.597 102.283,86.597 102.332,86.548 ; 102.169,89.401 102.677,89.401 ; 102.169,89.401 102.169,89.596 ; 102.169,89.596 102.169,90.104 ; 102.169,89.596 102.677,89.596 ; 102.169,90.104 102.169,90.612 ; 102.169,90.104 102.677,90.104 ; 102.169,90.612 102.169,91.12 ; 102.169,90.612 102.677,90.612 ; 102.169,91.12 102.169,91.628 ; 102.169,91.12 102.677,91.12 ; 102.169,91.628 102.169,92.136 ; 102.169,91.628 102.677,91.628 ; 102.169,92.136 102.169,92.644 ; 102.169,92.136 102.677,92.136 ; 102.169,92.644 102.169,93.152 ; 102.169,92.644 102.677,92.644 ; 102.169,93.152 102.169,93.66 ; 102.169,93.152 102.677,93.152 ; 102.169,93.66 102.169,94.168 ; 102.169,93.66 102.677,93.66 ; 102.169,94.168 102.169,94.676 ; 102.169,94.168 102.677,94.168 ; 102.169,94.676 102.169,95.184 ; 102.169,94.676 102.677,94.676 ; 102.169,95.184 102.677,95.184 ; 102.169,95.184 pad.@102.169,95.692 ; pad.@102.169,95.692 pad.@102.169,95.819 ; pad.@102.169,95.692 pad.@102.677,95.692 ; pad.@102.169,95.819 102.296,95.946 102.677,95.946 ; 102.677,62.932 102.677,63.18 ; 102.677,62.932 103.185,62.932 ; 102.677,63.18 102.677,63.688 ; 102.677,63.18 103.185,63.18 ; 102.677,63.688 102.677,64.196 ; 102.677,63.688 103.185,63.688 ; 102.677,64.196 C72.2@103.185,64.196 ; 102.677,64.196 102.677,64.704 ; 102.677,64.704 102.677,65.212 ; 102.677,64.704 C72.2@103.185,64.704 ; 102.677,65.212 102.677,65.72 ; 102.677,65.212 C72.2@103.185,65.212 ; 102.677,65.72 C73.2@102.677,66.228 ; 102.677,65.72 103.185,65.72 ; C73.2@102.677,66.228 C73.2@103.185,66.228 ; C73.2@102.677,66.228 C73.2@102.677,66.736 ; C73.2@102.677,66.736 C73.2@103.185,66.736 ; C73.2@102.677,66.736 C73.2@102.677,67.244 ; C73.2@102.677,67.244 102.677,67.752 ; C73.2@102.677,67.244 C73.2@103.185,67.244 ; 102.677,67.752 102.677,68.26 ; 102.677,67.752 103.185,67.752 ; 102.677,68.26 102.677,68.768 ; 102.677,68.26 C70.2@103.185,68.26 ; 102.677,68.768 C70.2@103.185,68.768 ; 102.677,68.768 102.677,69.276 ; 102.677,69.276 103.007,69.276 C70.2@103.185,69.276 ; 102.677,69.276 102.677,69.606 102.677,69.784 ; 102.677,69.784 102.677,69.802 ; 102.677,69.784 103.185,69.784 ; 102.677,69.802 103.185,69.802 ; 102.677,80.484 102.722,80.484 103.185,80.484 ; 102.677,80.484 102.677,80.53 102.677,80.96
